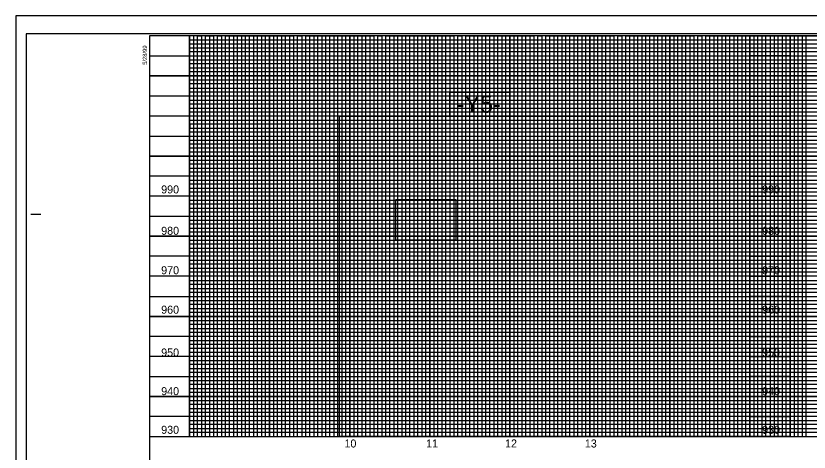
# Model space of a CAD drawing. Extents: x 1621288 to 1629363, y 896995 to 899414.
# Drawn here: x 1627302 to 1628293, y 897550 to 898095 of the extents above; entities that cross this region are included whole.
import ezdxf

# ---------------------------------------------------------------- set-up
doc = ezdxf.new("R2010")
doc.units = 0
for name, color, linetype in [('Exist Profile Cell', 7, 'Continuous'), ('Exist Structure Minor Pipes CMAP 112inx75in', 7, 'Continuous'), ('Exist Vertical Profile Horizontal Axis Label Major', 7, 'Continuous'), ('Exist XS Ground Line', 7, 'Continuous'), ('Prop Horizontal Alignment', 7, 'Continuous'), ('Prop Horizontal Alignment Curve and Spiral Data', 7, 'Continuous'), ('Prop Vertical Profile Curve Label', 7, 'Continuous'), ('Prop Vertical Profile Grade', 7, 'Continuous'), ('Prop VPI Label', 7, 'Continuous'), ('Sheet Layout Plan Border', 7, 'Continuous'), ('Sheet Layout Profile Border', 7, 'Continuous'), ('Sheet Layout Profile Border Port 2', 7, 'Continuous')]:
    doc.layers.add(name, color=color, linetype=linetype)

msp = doc.modelspace()

# ---------------------------------------------------------------- linework, layer by layer
at = {"layer": 'Exist Profile Cell'}
for p, q in [((1627519.38, 898064.66), (1628769.38, 898064.66)), ((1627519.38, 898059.66), (1627519.38, 898059.66)), ((1628769.38, 898059.66), (1627519.38, 898059.31)), ((1627519.38, 898054.66), (1628769.38, 898054.66)), ((1628769.33, 897934.66), (1627519.38, 897934.66)), ((1628769.38, 897929.66), (1627519.38, 897929.66)), ((1628769.38, 897924.66), (1627519.38, 897924.66)), ((1627519.38, 897914.66), (1628769.38, 897914.66)), ((1628769.38, 897909.66), (1627519.38, 897909.66)), ((1627519.38, 897904.66), (1628919.38, 897904.66)), ((1628919.38, 897884.66), (1627519.38, 897884.66)), ((1627519.38, 897879.66), (1628919.38, 897879.66)), ((1628919.38, 897859.66), (1627519.38, 897859.66)), ((1627519.38, 897854.66), (1628919.38, 897854.66)), ((1628919.38, 897834.66), (1627519.38, 897834.66)), ((1627519.38, 897829.66), (1628919.38, 897829.66)), ((1628919.38, 897824.66), (1627519.38, 897824.66)), ((1627519.38, 897814.66), (1628919.38, 897814.66)), ((1628919.38, 897809.66), (1627519.38, 897809.66)), ((1627519.38, 897804.66), (1628919.38, 897804.66)), ((1628919.38, 897799.66), (1627519.38, 897799.66)), ((1627519.38, 897789.66), (1628919.38, 897789.66)), ((1628919.38, 897784.66), (1627519.38, 897784.66)), ((1627519.38, 897779.66), (1628919.38, 897779.66)), ((1628919.38, 897774.66), (1627519.38, 897774.66)), ((1627519.38, 897764.66), (1628919.38, 897764.66)), ((1628919.38, 897759.66), (1627519.38, 897759.66)), ((1627519.38, 897754.66), (1628919.38, 897754.66)), ((1628919.38, 897749.66), (1627519.38, 897749.66)), ((1627519.38, 897739.66), (1628919.38, 897739.66)), ((1628919.38, 897734.66), (1627519.38, 897734.66)), ((1627519.38, 897729.66), (1628919.38, 897729.66)), ((1628919.38, 897724.66), (1627519.38, 897724.66)), ((1627519.38, 897714.66), (1628919.38, 897714.66)), ((1628919.38, 897709.66), (1627519.38, 897709.66)), ((1627519.38, 897704.66), (1628919.38, 897704.66)), ((1628919.38, 897699.66), (1627519.38, 897699.66)), ((1627519.38, 897689.66), (1628919.38, 897689.66)), ((1628919.38, 897684.66), (1627519.38, 897684.66)), ((1628919.38, 897679.66), (1627519.38, 897679.66)), ((1628919.38, 897674.66), (1627519.38, 897674.66)), ((1627519.38, 897664.66), (1628919.38, 897664.66)), ((1628919.38, 897659.66), (1627519.38, 897659.66)), ((1627519.38, 897654.66), (1628919.38, 897654.66)), ((1628919.38, 897649.66), (1627519.38, 897649.66)), ((1627519.38, 897639.66), (1628919.38, 897639.66)), ((1628919.38, 897634.66), (1627519.38, 897634.66)), ((1627519.38, 897629.66), (1628919.38, 897629.66)), ((1628919.38, 897624.66), (1627519.38, 897624.66)), ((1627519.38, 897614.66), (1628919.38, 897614.66)), ((1628919.38, 897609.66), (1627519.38, 897609.66)), ((1627519.38, 897604.66), (1628919.38, 897604.66)), ((1628919.38, 897599.66), (1627519.38, 897599.66)), ((1627519.38, 897589.66), (1628919.38, 897589.66)), ((1628919.38, 897584.66), (1627519.38, 897584.66)), ((1627519.38, 897579.66), (1628919.38, 897579.66))]:
    msp.add_line(p, q, dxfattribs=at)
for points in [[(1627524.38, 898069.66), (1627524.38, 897569.66), (1627529.38, 897569.66), (1627529.38, 898069.66), (1627534.38, 898069.66), (1627534.38, 897569.66), (1627539.38, 897569.66), (1627539.38, 898069.66), (1627549.38, 898069.66), (1627549.38, 897569.66), (1627554.38, 897569.66), (1627554.38, 898069.66), (1627559.38, 898069.66), (1627559.38, 897569.66), (1627564.38, 897569.66), (1627574.38, 897569.66), (1627579.38, 897569.66), (1627579.38, 898069.66), (1627584.38, 898069.66), (1627584.38, 897569.66), (1627589.38, 897569.66), (1627589.38, 898069.66), (1627599.38, 898069.66), (1627599.38, 897569.66), (1627604.38, 897569.66), (1627604.38, 898069.66), (1627609.38, 898069.66), (1627609.38, 897569.66), (1627614.38, 897569.66), (1627614.38, 898069.66), (1627624.38, 898069.66), (1627624.38, 897569.66), (1627629.38, 897569.66), (1627629.38, 898069.66), (1627634.38, 898069.66), (1627634.38, 897569.66), (1627639.38, 897569.66), (1627639.38, 898069.66), (1627649.38, 898069.66), (1627649.38, 897569.66), (1627654.38, 897569.66), (1627654.38, 898069.66), (1627659.38, 898069.66), (1627659.38, 897569.66), (1627664.38, 897569.66), (1627664.38, 898069.66), (1627674.38, 898069.66), (1627674.38, 897569.66), (1627679.38, 897569.66), (1627679.38, 898069.66), (1627684.38, 898069.66), (1627684.38, 897569.66), (1627689.38, 897569.66), (1627689.38, 898069.66), (1627699.38, 898069.66), (1627699.38, 897569.66), (1627704.38, 897569.66), (1627704.38, 898069.66), (1627709.38, 898069.66), (1627709.38, 897569.66), (1627714.38, 897569.66), (1627714.38, 898069.66), (1627724.38, 898069.66), (1627724.38, 897569.66), (1627729.38, 897569.66), (1627729.38, 898069.66), (1627734.38, 898069.66), (1627734.38, 897569.66)], [(1627564.38, 897569.66), (1627564.38, 898069.66), (1627574.38, 898069.66), (1627574.38, 897569.66)], [(1627734.38, 897569.66), (1627739.38, 897569.66), (1627739.38, 898069.66), (1627749.38, 898069.66), (1627749.38, 897569.66), (1627754.38, 897569.66), (1627754.38, 898069.66), (1627759.38, 898069.66), (1627759.38, 897569.66), (1627764.38, 897569.66), (1627764.38, 898069.66), (1627774.38, 898069.66), (1627774.38, 897569.66), (1627779.38, 897569.66), (1627779.38, 898069.66), (1627784.38, 898069.66), (1627784.38, 897569.66), (1627789.38, 897569.66), (1627789.38, 898069.66), (1627799.38, 898069.66), (1627799.38, 897569.66), (1627804.38, 897569.66), (1627804.38, 898069.66), (1627809.38, 898069.66), (1627809.38, 897569.66), (1627814.38, 897569.66), (1627814.38, 898069.66), (1627824.38, 898069.66), (1627824.38, 897569.66), (1627829.38, 897569.66), (1627829.38, 898069.66), (1627834.38, 898069.66), (1627834.38, 897569.66), (1627839.38, 897569.66), (1627839.38, 898069.66), (1627849.38, 898069.66), (1627849.38, 897569.66), (1627854.38, 897569.66), (1627854.38, 898069.66), (1627859.38, 898069.66), (1627859.38, 897569.66), (1627864.38, 897569.66), (1627864.38, 898069.66), (1627874.38, 898069.66), (1627874.38, 897569.66), (1627879.38, 897569.66), (1627879.38, 898069.66), (1627884.38, 898069.66), (1627884.38, 897569.66), (1627889.38, 897569.66), (1627889.38, 898069.66), (1627899.38, 898069.66), (1627899.38, 897569.66), (1627904.38, 897569.66), (1627904.38, 898069.66), (1627909.38, 898069.66), (1627909.38, 897569.66), (1627914.38, 897569.66), (1627914.38, 898069.66), (1627924.38, 898069.66), (1627924.38, 897569.66), (1627929.38, 897569.66), (1627929.38, 898069.66), (1627934.38, 898069.66), (1627934.38, 897569.66), (1627939.38, 897569.66), (1627939.38, 898069.66), (1627949.38, 898069.66), (1627949.38, 897569.66), (1627954.38, 897569.66), (1627954.38, 898069.66), (1627959.38, 898069.66), (1627959.38, 897569.66), (1627964.38, 897569.66), (1627964.38, 898069.66), (1627974.38, 898069.66), (1627974.38, 897569.66), (1627979.38, 897569.66), (1627979.38, 898069.66), (1627984.38, 898069.66), (1627984.38, 897569.66), (1627989.38, 897569.66), (1627989.38, 898069.66), (1627999.38, 898069.66), (1627999.38, 897569.66), (1628004.38, 897569.66), (1628004.38, 898069.66), (1628009.38, 898069.66), (1628009.38, 897569.66), (1628014.38, 897569.66), (1628014.38, 898069.66), (1628024.38, 898069.66), (1628024.38, 897569.66), (1628029.38, 897569.66), (1628029.38, 898069.66), (1628034.38, 898069.66), (1628034.38, 897569.66), (1628039.38, 897569.66), (1628039.38, 898069.66), (1628049.38, 898069.66)], [(1628049.38, 898069.66), (1628049.38, 897569.66), (1628054.38, 897569.66), (1628054.38, 898069.66), (1628059.38, 898069.66), (1628059.38, 897569.66), (1628064.38, 897569.66), (1628064.38, 898069.66), (1628074.38, 898069.66), (1628074.38, 897569.66), (1628079.38, 897569.66), (1628079.38, 898069.66), (1628084.38, 898069.66), (1628084.38, 897569.66), (1628089.38, 897569.66), (1628089.38, 898069.66), (1628099.38, 898069.66), (1628099.38, 897569.66), (1628104.38, 897569.66), (1628104.38, 898069.66), (1628109.38, 898069.66), (1628109.38, 897569.66), (1628114.38, 897569.66), (1628114.38, 898069.66), (1628124.38, 898069.66), (1628124.38, 897569.66), (1628129.38, 897569.66), (1628129.38, 898069.66), (1628134.38, 898069.66), (1628134.38, 897569.66), (1628139.38, 897569.66), (1628139.38, 898069.66), (1628149.38, 898069.66), (1628149.38, 897569.66), (1628154.38, 897569.66), (1628154.38, 898069.66), (1628159.38, 898069.66), (1628159.38, 897569.66), (1628164.38, 897569.66), (1628164.38, 898069.66), (1628174.38, 898069.66), (1628174.38, 897569.66), (1628174.38, 897569.66), (1628179.38, 897569.66), (1628179.38, 898069.66), (1628184.38, 898069.66), (1628184.38, 897569.66), (1628189.38, 897569.66), (1628189.38, 898069.66), (1628199.38, 898069.66), (1628199.38, 897569.66), (1628204.38, 897569.66), (1628204.38, 898069.66), (1628209.38, 898069.66), (1628209.38, 897569.66), (1628214.38, 897569.66), (1628214.38, 898069.66), (1628224.38, 898069.66), (1628224.38, 897569.66), (1628229.38, 897569.66), (1628229.38, 898069.66), (1628234.38, 898069.66), (1628234.38, 897569.66), (1628239.38, 897569.66), (1628239.38, 898069.66), (1628249.38, 898069.66), (1628249.38, 897569.66), (1628254.38, 897569.66), (1628254.38, 898069.66), (1628259.38, 898069.66), (1628259.38, 897569.66), (1628264.38, 897569.66), (1628264.38, 898069.66), (1628274.38, 898069.66), (1628274.38, 897569.66), (1628279.38, 897569.66), (1628279.38, 898069.66), (1628284.38, 898069.66), (1628284.38, 897569.66), (1628289.38, 897569.66), (1628289.38, 898069.66), (1628299.38, 898069.66)], [(1628769.38, 898049.66), (1627519.38, 898049.66), (1627519.38, 898039.66), (1628769.38, 898039.66)], [(1628769.33, 898034.66), (1627519.38, 898034.66), (1627519.38, 898029.66), (1628769.38, 898029.66)], [(1628769.38, 898024.66), (1627519.38, 898024.66), (1627519.38, 898014.66), (1628769.38, 898014.66)], [(1628769.38, 898009.66), (1627519.38, 898009.66), (1627519.38, 898004.66), (1628769.38, 898004.66)], [(1628769.38, 897999.66), (1627519.38, 897999.66), (1627519.38, 897989.66), (1628769.38, 897989.66)], [(1628769.38, 897984.66), (1627519.38, 897984.66), (1627519.38, 897979.66), (1628769.38, 897979.66)], [(1628769.38, 897974.66), (1627519.38, 897974.66), (1627519.38, 897964.66), (1628769.38, 897964.66)], [(1628769.38, 897959.56), (1627519.48, 897959.56), (1627519.48, 897954.66), (1628769.38, 897954.66)], [(1628769.38, 897949.66), (1627519.38, 897949.66), (1627519.38, 897939.66), (1628769.38, 897939.66)], [(1628919.38, 897899.66), (1627519.38, 897899.66), (1627519.38, 897889.66), (1628919.38, 897889.66)], [(1628919.38, 897874.66), (1627519.38, 897874.66), (1627519.38, 897864.66), (1628919.38, 897864.66)], [(1628919.38, 897849.66), (1627519.38, 897849.66), (1627519.38, 897839.66), (1628919.38, 897839.66)], [(1628919.38, 897574.66), (1627519.38, 897574.66)]]:
    msp.add_lwpolyline(points, dxfattribs=at)
at = {"layer": 'Exist Structure Minor Pipes CMAP 112inx75in'}
msp.add_lwpolyline([(1627706.65, 897969.66), (1628219.38, 897969.66), (1628219.38, 897569.66), (1627706.65, 897569.66)], close=True, dxfattribs=at)
at = {"layer": 'Exist Vertical Profile Horizontal Axis Label Major'}
for points in [[(1628219.38, 898069.66), (1628269.38, 898069.66), (1628269.38, 898044.66), (1628219.38, 898044.66)], [(1628219.38, 898044.66), (1628269.38, 898044.66), (1628269.38, 898019.66), (1628219.38, 898019.66)], [(1628219.38, 898019.66), (1628269.38, 898019.66), (1628269.38, 897994.66), (1628219.38, 897994.66)], [(1627844.38, 897999.66), (1627919.38, 897999.66), (1627919.38, 897969.66), (1627844.38, 897969.66)], [(1628219.38, 897994.66), (1628269.38, 897994.66), (1628269.38, 897969.66), (1628219.38, 897969.66)], [(1628219.38, 897969.66), (1628269.38, 897969.66), (1628269.38, 897944.66), (1628219.38, 897944.66)], [(1628219.38, 897944.66), (1628269.38, 897944.66), (1628269.38, 897919.66), (1628219.38, 897919.66)], [(1628219.38, 897919.66), (1628269.38, 897919.66), (1628269.38, 897894.66), (1628219.38, 897894.66)], [(1628219.38, 897894.66), (1628269.38, 897894.66), (1628269.38, 897869.66), (1628219.38, 897869.66)], [(1627777.1, 897865.4), (1627851.94, 897865.4), (1627851.94, 897814.66), (1627777.1, 897814.66)], [(1628219.38, 897869.66), (1628269.38, 897869.66), (1628269.38, 897844.66), (1628219.38, 897844.66)], [(1628219.38, 897844.66), (1628269.38, 897844.66), (1628269.38, 897819.66), (1628219.38, 897819.66)], [(1628219.38, 897819.66), (1628269.38, 897819.66), (1628269.38, 897794.66), (1628219.38, 897794.66)], [(1628219.38, 897794.66), (1628269.38, 897794.66), (1628269.38, 897769.66), (1628219.38, 897769.66)], [(1628219.38, 897769.66), (1628269.38, 897769.66), (1628269.38, 897744.66), (1628219.38, 897744.66)], [(1628219.38, 897744.66), (1628269.38, 897744.66), (1628269.38, 897719.66), (1628219.38, 897719.66)], [(1628219.38, 897719.66), (1628269.38, 897719.66), (1628269.38, 897694.66), (1628219.38, 897694.66)], [(1628219.38, 897694.66), (1628269.38, 897694.66), (1628269.38, 897669.66), (1628219.38, 897669.66)], [(1628219.38, 897669.66), (1628269.38, 897669.66), (1628269.38, 897644.66), (1628219.38, 897644.66)], [(1628219.38, 897644.66), (1628269.38, 897644.66), (1628269.38, 897619.66), (1628219.38, 897619.66)], [(1628219.38, 897619.66), (1628269.38, 897619.66), (1628269.38, 897594.66), (1628219.38, 897594.66)], [(1628219.38, 897594.66), (1628269.38, 897594.66), (1628269.38, 897569.66), (1628219.38, 897569.66)]]:
    msp.add_lwpolyline(points, close=True, dxfattribs=at)
at = {"layer": 'Exist XS Ground Line'}
for p, q in [((1627320.88, 897847.16), (1627333.38, 897847.16)), ((1627469.38, 897569.66), (1628969.38, 897569.66))]:
    msp.add_line(p, q, dxfattribs=at)
msp.add_lwpolyline([(1628969.38, 898069.66), (1627469.38, 898069.66), (1627469.38, 897019.66), (1628969.38, 897019.66)], close=True, dxfattribs=at)
at = {"layer": 'Prop Horizontal Alignment'}
msp.add_lwpolyline([(1627519.38, 897908.61), (1627519.38, 897569.66), (1628919.38, 897569.66), (1628919.38, 897908.61)], dxfattribs=at)
at = {"layer": 'Prop Vertical Profile Curve Label'}
msp.add_lwpolyline([(1627315.38, 897017.11), (1628981.88, 897017.11), (1628981.88, 898072.21), (1627315.38, 898072.21)], close=True, dxfattribs=at)
at = {"layer": 'Prop Vertical Profile Grade'}
msp.add_line((1627469.38, 898044.66), (1628769.33, 898044.66), dxfattribs=at)
for points in [[(1627544.38, 898069.66), (1627544.38, 897569.66), (1627594.38, 897569.66), (1627594.38, 898069.66), (1627644.38, 898069.66), (1627644.38, 897569.66), (1627694.38, 897569.66), (1627694.38, 898069.66), (1627744.38, 898069.66), (1627744.38, 897569.66), (1627794.38, 897569.66), (1627794.38, 898069.66), (1627844.38, 898069.66), (1627844.38, 897569.66), (1627894.38, 897569.66), (1627894.38, 898069.66), (1627944.38, 898069.66), (1627944.38, 897569.66), (1627994.38, 897569.66), (1627994.38, 898069.66), (1628044.38, 898069.66), (1628044.38, 897569.66), (1628094.38, 897569.66), (1628094.38, 897569.66), (1628094.38, 898069.66), (1628144.38, 898069.66), (1628144.38, 897569.66), (1628194.38, 897569.66), (1628194.38, 898069.66), (1628244.38, 898069.66), (1628244.38, 897569.66), (1628294.38, 897569.66)], [(1628769.38, 897994.66), (1627469.38, 897994.66), (1627469.38, 897944.66), (1628769.38, 897944.66)], [(1628969.38, 897894.66), (1627469.38, 897894.66), (1627469.38, 897844.66), (1628794.38, 897844.66)], [(1628969.38, 897794.66), (1627469.38, 897794.66), (1627469.38, 897744.66), (1628969.38, 897744.66)], [(1628969.38, 897694.66), (1627469.38, 897694.66), (1627469.38, 897644.66), (1628969.38, 897644.66)], [(1628969.38, 897594.66), (1627469.38, 897594.66)]]:
    msp.add_lwpolyline(points, dxfattribs=at)
at = {"layer": 'Prop VPI Label'}
for p, q in [((1628219.38, 898044.66), (1628269.98, 898044.66)), ((1628219.38, 898019.66), (1628269.98, 898019.66)), ((1628219.38, 897994.66), (1628269.98, 897994.66)), ((1628219.38, 897969.66), (1628269.98, 897969.66)), ((1628219.38, 897944.66), (1628269.98, 897944.66)), ((1628219.38, 897919.66), (1628269.98, 897919.66)), ((1628219.38, 897894.66), (1628269.98, 897894.66)), ((1628219.38, 897869.66), (1628269.98, 897869.66)), ((1628219.38, 897844.66), (1628269.98, 897844.66)), ((1628219.38, 897819.66), (1628269.98, 897819.66)), ((1628219.38, 897794.66), (1628269.98, 897794.66)), ((1628219.38, 897769.66), (1628269.98, 897769.66)), ((1628219.38, 897744.66), (1628269.98, 897744.66)), ((1628219.38, 897719.66), (1628269.98, 897719.66)), ((1628219.38, 897694.66), (1628269.98, 897694.66)), ((1628219.38, 897669.66), (1628269.98, 897669.66)), ((1628219.38, 897644.66), (1628269.98, 897644.66)), ((1628219.38, 897619.66), (1628269.98, 897619.66)), ((1628219.38, 897594.66), (1628269.98, 897594.66))]:
    msp.add_line(p, q, dxfattribs=at)
for points in [[(1627519.38, 898069.66), (1627519.38, 897569.66), (1627569.38, 897569.66), (1627569.38, 898069.66), (1627619.38, 898069.66), (1627619.38, 897569.66), (1627669.38, 897569.66), (1627669.38, 898069.66), (1627719.38, 898069.66), (1627719.38, 897569.66), (1627769.38, 897569.66), (1627769.38, 898069.66), (1627819.38, 898069.66), (1627819.38, 897569.66), (1627869.38, 897569.66), (1627869.38, 898069.66), (1627919.38, 898069.66), (1627919.38, 897569.66), (1627969.38, 897569.66), (1627969.38, 898069.66), (1628019.38, 898069.66), (1628019.38, 897569.66), (1628069.38, 897569.66), (1628069.38, 898069.66), (1628119.38, 898069.66), (1628119.38, 897569.66), (1628169.38, 897569.66), (1628169.38, 898069.66), (1628219.38, 898069.66), (1628219.38, 897569.66), (1628269.38, 897569.66), (1628269.38, 898069.66), (1628319.38, 898069.66)], [(1627469.38, 898019.66), (1628769.38, 898019.66)], [(1628769.38, 897969.66), (1627469.38, 897969.66), (1627469.38, 897919.66), (1628769.38, 897919.66)], [(1628969.38, 897869.66), (1627469.38, 897869.66), (1627469.38, 897819.66), (1628969.38, 897819.66)], [(1628969.38, 897769.66), (1627469.38, 897769.66), (1627469.38, 897719.66), (1628969.38, 897719.66)], [(1628969.38, 897669.66), (1627469.38, 897669.66), (1627469.38, 897669.66), (1627469.38, 897619.66), (1628969.38, 897619.66)]]:
    msp.add_lwpolyline(points, dxfattribs=at)
at = {"layer": 'Sheet Layout Plan Border'}
msp.add_lwpolyline([(1627302.38, 896994.66), (1628986.38, 896994.66), (1628986.38, 898094.66), (1627302.38, 898094.66)], close=True, dxfattribs=at)
at = {"layer": 'Sheet Layout Profile Border'}
for p, q in [((1628986.38, 898094.66), (1627302.38, 898094.66)), ((1627302.38, 898094.66), (1627302.38, 896994.66))]:
    msp.add_line(p, q, dxfattribs=at)
at = {"layer": 'Sheet Layout Profile Border Port 2'}
for p, q in [((1627519.38, 897569.66), (1627519.38, 898069.66)), ((1627569.38, 897569.66), (1627569.38, 898069.66)), ((1627619.38, 897569.66), (1627619.38, 898069.66)), ((1627669.38, 897569.66), (1627669.38, 898069.66)), ((1627719.38, 897569.66), (1627719.38, 898069.66)), ((1627769.38, 897569.66), (1627769.38, 898069.66)), ((1627819.38, 897569.66), (1627819.38, 898069.66)), ((1627869.38, 897569.66), (1627869.38, 898069.66)), ((1627919.38, 897569.66), (1627919.38, 898069.66)), ((1627969.38, 897569.66), (1627969.38, 898069.66)), ((1628019.38, 897569.66), (1628019.38, 898069.66)), ((1628069.38, 897569.66), (1628069.38, 898069.66)), ((1628119.38, 897569.66), (1628119.38, 898069.66)), ((1628169.38, 897569.66), (1628169.38, 898069.66)), ((1628219.38, 897569.66), (1628219.38, 898069.66)), ((1628269.38, 897569.66), (1628269.38, 898069.66)), ((1628769.33, 898019.66), (1627469.38, 898019.66)), ((1628769.33, 897969.66), (1627469.38, 897969.66)), ((1628769.38, 897919.66), (1627469.38, 897919.66)), ((1628969.38, 897869.66), (1627469.38, 897869.66)), ((1628969.38, 897819.66), (1627469.38, 897819.66)), ((1628969.38, 897769.66), (1627469.38, 897769.66)), ((1628969.38, 897719.66), (1627469.38, 897719.66)), ((1628969.38, 897669.66), (1627469.38, 897669.66)), ((1628969.38, 897619.66), (1627469.38, 897619.66))]:
    msp.add_line(p, q, dxfattribs=at)

# ---------------------------------------------------------------- texts
at = {"layer": 'Exist XS Ground Line'}
msp.add_text('5/28/99', height=5.25, rotation=90, dxfattribs=at).set_placement((1627466.14, 898033.57))
at = {"layer": 'Prop Horizontal Alignment Curve and Spiral Data'}
for s, height, p in [('-Y5-', 21.875, (1627852.93, 897973.72)), ('990', 10, (1627483.9, 897873.11)), ('990', 10, (1628234.51, 897873.11)), ('980', 10, (1627483.9, 897821.47)), ('980', 10, (1628234.51, 897821.47)), ('970', 10, (1627483.9, 897772.24)), ('970', 10, (1628234.51, 897772.24)), ('960', 10, (1627483.9, 897723.01)), ('960', 10, (1628234.51, 897723.01)), ('950', 10, (1627483.9, 897669.66)), ('950', 10, (1628234.51, 897669.66)), ('940', 10, (1627483.9, 897621.39)), ('940', 10, (1628234.51, 897621.39)), ('930', 10, (1627483.9, 897573.14)), ('930', 10, (1628234.51, 897573.14)), ('10', 10, (1627712.86, 897556.07)), ('11', 10, (1627814.83, 897556.07)), ('12', 10, (1627913.4, 897556.07)), ('13', 10, (1628013.07, 897556.07))]:
    msp.add_text(s, height=height, dxfattribs=at).set_placement(p)

doc.saveas('drawing.dxf')
